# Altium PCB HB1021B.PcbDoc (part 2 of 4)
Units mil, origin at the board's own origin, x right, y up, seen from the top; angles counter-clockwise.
Board outline 4729.44 x 3075.9 mil, 2 copper layers (Top Layer, Bottom Layer); 113 components, 113 nets, 422 pads, 478 vias.
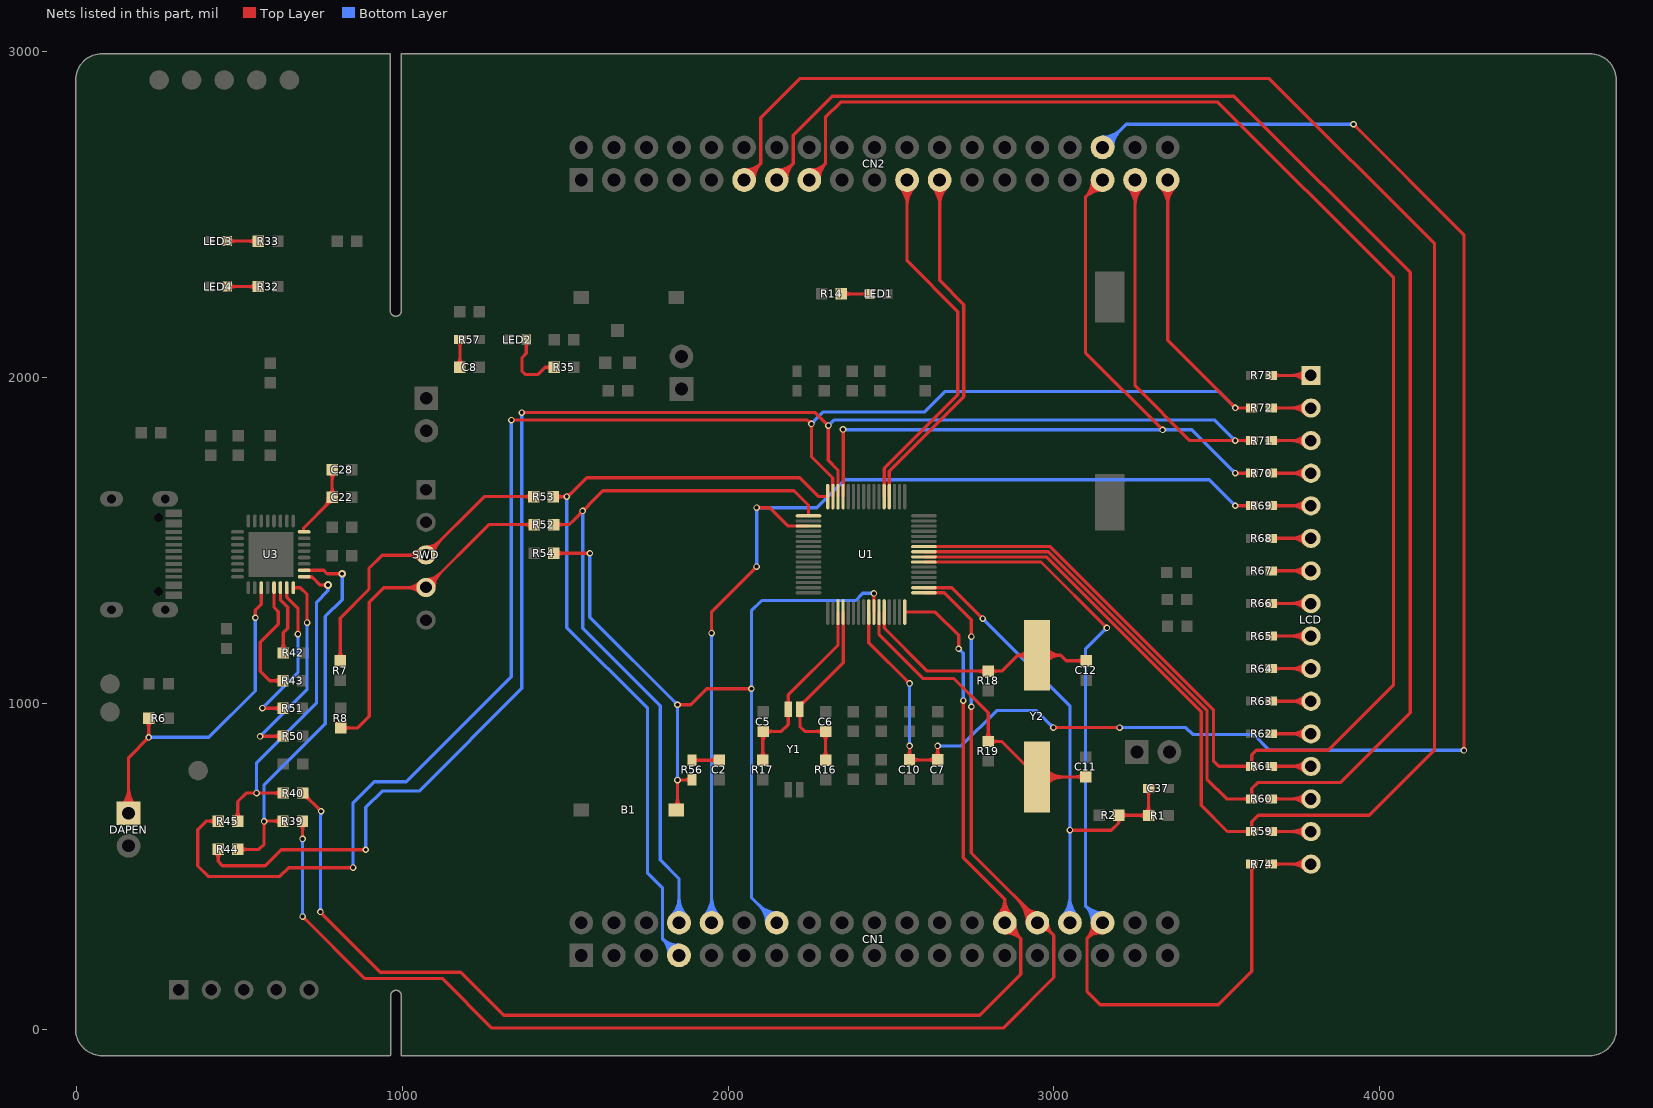
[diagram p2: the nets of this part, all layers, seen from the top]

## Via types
v1: diameter 20, hole 12, Top Layer to Bottom Layer, tented both sides, 451 vias
v2: diameter 23.62, hole 11.81, Top Layer to Bottom Layer, tented both sides, 20 vias
v3: diameter 122.05, hole 122.05, Top Layer to Bottom Layer, tented both sides, 4 vias
v4: diameter 39.37, hole 23.62, Top Layer to Bottom Layer, tented both sides, 2 vias
v5: diameter 30, hole 20, Top Layer to Bottom Layer, tented both sides, 1 vias

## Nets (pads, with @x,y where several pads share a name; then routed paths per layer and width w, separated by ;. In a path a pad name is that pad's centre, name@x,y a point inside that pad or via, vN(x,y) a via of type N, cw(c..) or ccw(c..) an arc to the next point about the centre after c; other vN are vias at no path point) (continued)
LINK_USART_RX: R39.1 R44.1 U3.26 | length 1393
  Top Layer w10: R44.1@495,552 560,552 576,568 v1(576,638) 577,639 R39.1@634,639 ; R44.1@503.84,543.16 cw(c525.18,521.82) 525.18,552 cw(c525.18,582.18) R44.1@503.84,560.84 ; v1@572.46,634.46 cw(c563.93,625.93) 576,625.93 cw(c588.07,625.93) 579.54,634.46 cw(c590.49,623.51) 590.49,639 ; R39.1@625.16,630.16 ccw(c603.82,608.82) 603.82,639 ccw(c603.82,669.18) R39.1@625.16,647.84 ; U3.26@698.97,1408.57 758.82,1408.57 769.09,1398.31 v2(815.61,1398.31) ; v2@810.79,1393.49 ccw(c799.16,1381.86) 799.16,1398.31 ccw(c799.16,1414.75) v2@810.79,1403.12
  Bottom Layer w10: v1@572.46,641.54 ccw(c563.93,650.07) 576,650.07 ccw(c588.07,650.07) v1@579.54,641.54 ; v1(576,638) 576,750 764.06,938.06 764.06,1267.06 815.61,1318.61 v2(815.61,1398.31) ; v2@810.79,1393.49 cw(c799.16,1381.86) 815.61,1381.86 cw(c832.05,1381.86) v2@820.42,1393.49
LINK_USART_TX: R40.1 R45.1 U3.25 | length 1264.5
  Top Layer w10: R45.1@486.16,647.84 ccw(c464.82,669.18) 495,669.18 ccw(c525.18,669.18) R45.1@503.84,647.84 ; R45.1@495,639 495,699 521,725 v1(553,725) R40.1@635,725 ; v1@549.46,721.46 ccw(c540.93,712.93) 540.93,725 ccw(c540.93,737.07) v1@549.46,728.54 ; v1@556.54,721.46 cw(c565.07,712.93) 565.07,725 cw(c565.07,737.07) v1@556.54,728.54 ; R40.1@626.16,716.16 ccw(c604.82,694.82) 604.82,725 ccw(c604.82,755.18) R40.1@626.16,733.84 ; U3.25@697,1388.89 U3.25@698.97,1388.89 723.02,1388.89 748.61,1363.31 v2(772,1363.31) ; U3.25@713.14,1388.38 cw(c713.14,1363.28) 730.89,1381.03 ; U3.25@713.24,1388.39 cw(c716.47,1372.45) 727.97,1383.95 ; v2@767.18,1358.49 ccw(c755.56,1346.86) 755.56,1363.31 ccw(c755.56,1379.75) v2@767.18,1368.12
  Bottom Layer w10: v1@549.46,728.54 ccw(c540.93,737.07) 553,737.07 ccw(c565.07,737.07) v1@556.54,728.54 ; v1(553,725) 553,818 737,1002 737,1311 772,1346 v2(772,1363.31) ; v2@767.18,1358.49 cw(c755.56,1346.86) 772,1346.86 cw(c788.44,1346.86) v2@776.82,1358.49
LXTAL_IN: C5.2 R17.2 U1.3 Y1.1 | length 776.8
  Top Layer w10: R17.2@2098.16,834.84 ccw(c2076.82,856.18) 2107,856.18 ccw(c2137.18,856.18) R17.2@2115.84,834.84 ; C5.2@2099.16,905.16 cw(c2080.23,886.23) 2107,886.23 ; R17.2@2107,826 2107,913 C5.2@2108,914 2164,914 2185.27,935.27 Y1.1@2185.27,982.79 2185.27,1026.27 2337.65,1178.65 U1.3@2337.65,1280.62 ; 2107,881.41 cw(c2140.59,881.41) 2116.84,905.16 cw(c2138.18,883.82) 2138.18,914 cw(c2138.18,944.18) C5.2@2116.84,922.84 ; Y1.1@2180.45,966.16 cw(c2168.83,954.53) 2185.27,954.53 cw(c2201.71,954.53) Y1.1@2190.08,966.16 ; Y1.1@2180.45,999.42 ccw(c2168.83,1011.04) 2185.27,1011.04 ccw(c2201.71,1011.04) Y1.1@2190.08,999.42
LXTAL_OUT: C6.2 R16.2 U1.4 Y1.4 | length 766
  Top Layer w10: Y1.4@2215.88,966.16 cw(c2204.26,954.53) 2220.7,954.53 cw(c2237.14,954.53) Y1.4@2225.52,966.16 ; Y1.4@2220.7,1001.41 ccw(c2220.7,1024.85) 2237.28,1008.28 ; R16.2@2290.77,834.84 ccw(c2269.43,856.17) 2299.61,856.17 ; C6.2@2290.77,922.84 cw(c2269.43,944.18) 2269.43,914 cw(c2269.43,883.82) 2290.77,905.16 cw(c2269.43,883.82) 2299.61,883.82 cw(c2329.78,883.82) C6.2@2308.44,905.16 ; R16.2@2299.61,826 C6.2@2299.61,914 2236,914 2220.7,929.3 Y1.4@2220.7,982.79 2220.7,991.7 2353.4,1124.4 U1.4@2353.4,1280.62 ; 2299.61,856.18 ccw(c2329.79,856.18) R16.2@2308.45,834.84
MCU_SWCLK: R8.2 R52.1 SWD.4 | length 1447.2
  Top Layer w10: R8.2@811,925 863,925 899,961 899,1311 943.21,1355.21 SWD.4@1072,1355.21 ; R8.2@819.84,916.16 cw(c841.18,894.82) 841.18,925 cw(c841.18,955.18) R8.2@819.84,933.84 ; 1011.88,1355.21 ccw(c1011.88,1417.12) SWD.4@1055.66,1373.34 ; 1015.69,1355.21 cw(c1015.69,1298.69) SWD.4@1055.66,1338.66 ; 1036.02,1355.21 ccw(c1036.02,1392.98) SWD.4@1062.73,1366.27 ; 1039.83,1355.21 cw(c1039.83,1322.83) SWD.4@1062.73,1345.73 ; SWD.4@1073,1356 1266,1549 R52.1@1405,1549 ; SWD.4@1073,1370.53 ccw(c1073,1405.6) 1097.8,1380.8 ccw(c1122.6,1356) SWD.4@1087.53,1356 ; SWD.4@1073,1380.53 ccw(c1073,1439.74) 1114.87,1397.87 ccw(c1156.74,1356) SWD.4@1097.53,1356 ; R52.1@1396.16,1540.16 ccw(c1374.82,1518.82) 1374.82,1549 ccw(c1374.82,1579.18) R52.1@1396.16,1557.84
MCU_SWDIO: R7.2 R53.1 SWD.3 | length 1307.3
  Top Layer w10: R7.2@801.16,1139.84 ccw(c779.82,1161.18) 810,1161.18 ccw(c840.18,1161.18) R7.2@818.84,1139.84 ; R7.2@810,1131 810,1261.92 898.07,1349.99 898.07,1415.07 938.21,1455.21 SWD.3@1072,1455.21 ; 1011.88,1455.21 ccw(c1011.88,1517.12) SWD.3@1055.66,1473.34 ; 1015.69,1455.21 cw(c1015.69,1398.69) SWD.3@1055.66,1438.66 ; 1036.02,1455.21 ccw(c1036.02,1492.98) SWD.3@1062.73,1466.27 ; 1039.83,1455.21 cw(c1039.83,1422.83) SWD.3@1062.73,1445.73 ; SWD.3@1073,1456 1252,1635 R53.1@1404,1635 ; SWD.3@1073,1470.53 ccw(c1073,1505.6) 1097.8,1480.8 ccw(c1122.6,1456) SWD.3@1087.53,1456 ; SWD.3@1073,1480.53 ccw(c1073,1539.74) 1114.87,1497.87 ccw(c1156.74,1456) SWD.3@1097.53,1456 ; R53.1@1395.16,1626.16 ccw(c1373.82,1604.82) 1373.82,1635 ccw(c1373.82,1665.18) R53.1@1395.16,1643.84
NetC2_1: C2.1 R56.2 | length 163.7
  Top Layer w10: R56.2@1890,826 C2.1@1973,826 ; R56.2@1896.21,819.79 cw(c1911.2,804.8) 1911.2,826 cw(c1911.2,847.19) R56.2@1896.21,832.21 ; C2.1@1964.16,817.16 ccw(c1942.82,795.82) 1942.82,826 ccw(c1942.82,856.18) C2.1@1964.16,834.84
NetC8_2: C8.2 R57.2 | length 165.7
  Top Layer w10: C8.2@1168.16,2040.84 ccw(c1146.82,2062.18) 1177,2062.18 ccw(c1207.18,2062.18) C8.2@1185.84,2040.84 ; R57.2@1170.79,2110.79 cw(c1155.81,2095.81) 1177,2095.81 cw(c1198.2,2095.81) R57.2@1183.21,2110.79 ; C8.2@1177,2032 R57.2@1177,2117
NetC11_1: C11.1 R19.1 U1.11 Y2.1 | length 1302.2
  Top Layer w10: U1.11@2463.64,1280.62 2463.64,1211.36 2598.69,1076.31 2693.69,1076.31 2798.61,971.39 R19.1@2798.61,883.31 ; R19.1@2789.77,892.15 ccw(c2768.43,913.48) 2798.61,913.48 ccw(c2828.78,913.48) 2807.45,892.15 ccw(c2828.79,913.49) 2828.79,883.31 ccw(c2828.78,853.13) R19.1@2807.45,874.47 ; R19.1@2797.69,883.31 2839.6,883.31 Y2.1@2948.61,774.3 3096.6,774.3 C11.1@3097.61,775.31 ; Y2.1@2965.84,757.07 cw(c3007.44,715.47) 3007.44,774.3 cw(c3007.44,833.13) Y2.1@2965.84,791.53 ; Y2.1@2972.91,750 cw(c3031.58,691.32) 3031.58,774.3 cw(c3031.58,857.28) Y2.1@2972.91,798.6 ; 3065,774.3 ccw(c3065,807.91) C11.1@3088.77,784.14 ; 3069.86,774.3 cw(c3069.86,747.56) C11.1@3088.77,766.47
NetC12_1: C12.1 R18.1 U1.12 Y2.2 | length 1192.2
  Top Layer w10: U1.12@2479.39,1280.62 2479.39,1231.61 2611.69,1099.31 2840.61,1099.31 2889.61,1148.31 ; R18.1@2789.77,1090.47 ccw(c2768.43,1069.13) 2768.43,1099.31 ccw(c2768.43,1129.48) R18.1@2789.77,1108.15 ; R18.1@2807.44,1090.47 cw(c2828.78,1069.13) 2828.78,1099.31 cw(c2828.78,1129.48) R18.1@2807.45,1108.15 ; Y2.2@2918.71,1131.36 ccw(c2889.61,1114.87) 2889.61,1148.31 ; Y2.2@2918.71,1165.26 cw(c2889.61,1181.76) 2889.61,1148.31 ; Y2.2@2927.41,1136.3 ccw(c2906.78,1124.6) 2906.78,1148.31 ccw(c2906.78,1172.03) Y2.2@2927.41,1160.33 ; Y2.2@2967.53,1132.95 cw(c2999.78,1106.77) 2999.78,1148.31 cw(c2999.78,1189.85) Y2.2@2967.53,1163.67 ; Y2.2@2975.29,1126.65 cw(c3020.78,1089.73) 3020.78,1148.31 ; Y2.2@2975.29,1169.98 ccw(c3020.78,1206.9) 3020.78,1148.31 ; C12.1@3090.77,1122.47 ccw(c3069.43,1101.13) 3069.43,1131.31 ccw(c3069.43,1161.49) C12.1@3090.77,1140.15 ; C12.1@3099.61,1131.31 3037.79,1131.31 3020.78,1148.31 ; 2889.61,1148.31 Y2.2@2948.61,1148.31 3020.78,1148.31
NetC22_2: C22.2 C28.2 U3.32 | length 369.8
  Top Layer w10: U3.32@697,1526.68 697,1538.18 781.11,1622.29 784.61,1625.79 C28.2@784.61,1711.79 ; 697,1532.67 ccw(c704.96,1532.67) U3.32@699.33,1527.05 ; 760.02,1601.21 ccw(c728.44,1632.79) C22.2@773.11,1632.79 ; C22.2@774.51,1615.69 cw(c785.61,1604.6) C22.2@785.61,1620.29 ; C22.2@776.77,1641.63 ccw(c757.84,1660.55) 784.61,1660.55 ; C28.2@776.77,1707.95 cw(c757.84,1689.02) 784.61,1689.02 ; 784.61,1665.38 ccw(c818.2,1665.38) C22.2@794.45,1641.63 ; 784.61,1684.2 cw(c818.2,1684.2) C28.2@794.45,1707.95
NetDAPEN_1: DAPEN.1 R6.1 U3.19 | length 1370.8
  Top Layer w10: DAPEN.1@137.78,685.22 ccw(c84.15,738.85) 160,738.85 ccw(c235.85,738.85) DAPEN.1@182.22,685.22 ; DAPEN.1@144.86,678.14 ccw(c108.29,714.71) 160,714.71 ccw(c211.71,714.71) DAPEN.1@175.14,678.14 ; DAPEN.1@160,663 160,834 v1(222,896) R6.1@222,955 ; R6.1@213.16,946.16 cw(c191.82,924.82) 222,924.82 cw(c252.18,924.82) R6.1@230.84,946.16 ; v1@217,896 cw(c204.93,896) 213.46,887.46 cw(c222,878.93) v1@222,891 ; v1@218.46,899.53 ccw(c209.93,908.07) 222,908.07 ccw(c234.07,908.07) v1@225.53,899.53 ; v1@545.46,1266.54 ccw(c536.93,1275.07) 549,1275.07 ccw(c561.07,1275.07) v1@552.54,1266.54 ; v1(549,1263) 549,1285.86 567.08,1303.93 U3.19@567.08,1355.43
  Bottom Layer w10: v1(222,896) 406.71,896 549,1038.28 v1(549,1263) ; v1@225.53,892.46 cw(c234.07,883.93) 234.07,896 cw(c234.07,908.07) v1@225.53,899.53 ; v1@545.46,1259.46 cw(c536.93,1250.93) 549,1250.93 cw(c561.07,1250.93) v1@552.54,1259.46
NetLCD_1: LCD.1 R73.2 | length 302.6
  Top Layer w10: R73.2@3668,2007 LCD.1@3789.2,2007 ; R73.2@3677.93,2000.79 cw(c3692.92,1985.8) 3692.92,2007 cw(c3692.92,2028.2) R73.2@3677.93,2013.21 ; 3729.62,2007 cw(c3729.62,1946.9) LCD.1@3772.11,1989.4 ; 3730.87,2007 ccw(c3730.87,2065.33) LCD.1@3772.11,2024.08 ; 3753.76,2007 cw(c3753.76,1971.04) LCD.1@3779.18,1996.47 ; 3755.01,2007 ccw(c3755.01,2041.19) LCD.1@3779.18,2017.01
NetLCD_2: LCD.2 R72.2 | length 302.6
  Top Layer w10: R72.2@3668,1907 LCD.2@3789.2,1907 ; R72.2@3677.93,1900.79 cw(c3692.92,1885.8) 3692.92,1907 cw(c3692.92,1928.2) R72.2@3677.93,1913.21 ; 3729.62,1907 cw(c3729.62,1846.9) LCD.2@3772.11,1889.4 ; 3730.87,1907 ccw(c3730.87,1965.33) LCD.2@3772.11,1924.08 ; 3753.76,1907 cw(c3753.76,1871.04) LCD.2@3779.18,1896.47 ; 3755.01,1907 ccw(c3755.01,1941.19) LCD.2@3779.18,1917.01
NetLCD_3: LCD.3 R71.2 | length 302.6
  Top Layer w10: R71.2@3668,1807 LCD.3@3789.2,1807 ; R71.2@3677.93,1800.79 cw(c3692.92,1785.8) 3692.92,1807 cw(c3692.92,1828.2) R71.2@3677.93,1813.21 ; 3729.62,1807 cw(c3729.62,1746.9) LCD.3@3772.11,1789.4 ; 3730.87,1807 ccw(c3730.87,1865.33) LCD.3@3772.11,1824.08 ; 3753.76,1807 cw(c3753.76,1771.04) LCD.3@3779.18,1796.47 ; 3755.01,1807 ccw(c3755.01,1841.19) LCD.3@3779.18,1817.01
NetLCD_4: LCD.4 R70.2 | length 302.6
  Top Layer w10: R70.2@3668,1707 LCD.4@3789.2,1707 ; R70.2@3677.93,1700.79 cw(c3692.92,1685.8) 3692.92,1707 cw(c3692.92,1728.2) R70.2@3677.93,1713.21 ; 3729.62,1707 cw(c3729.62,1646.9) LCD.4@3772.11,1689.4 ; 3730.87,1707 ccw(c3730.87,1765.33) LCD.4@3772.11,1724.08 ; 3753.76,1707 cw(c3753.76,1671.04) LCD.4@3779.18,1696.47 ; 3755.01,1707 ccw(c3755.01,1741.19) LCD.4@3779.18,1717.01
NetLCD_5: LCD.5 R69.2 | length 302.6
  Top Layer w10: R69.2@3668,1607 LCD.5@3789.2,1607 ; R69.2@3677.93,1600.79 cw(c3692.92,1585.8) 3692.92,1607 cw(c3692.92,1628.2) R69.2@3677.93,1613.21 ; 3729.62,1607 cw(c3729.62,1546.9) LCD.5@3772.11,1589.4 ; 3730.87,1607 ccw(c3730.87,1665.33) LCD.5@3772.11,1624.08 ; 3753.76,1607 cw(c3753.76,1571.04) LCD.5@3779.18,1596.47 ; 3755.01,1607 ccw(c3755.01,1641.19) LCD.5@3779.18,1617.01
NetLCD_6: LCD.6 R68.2 | length 302.6
  Top Layer w10: R68.2@3668,1507 LCD.6@3789.2,1507 ; R68.2@3677.93,1500.79 cw(c3692.92,1485.8) 3692.92,1507 cw(c3692.92,1528.2) R68.2@3677.93,1513.21 ; 3729.62,1507 cw(c3729.62,1446.9) LCD.6@3772.11,1489.4 ; 3730.87,1507 ccw(c3730.87,1565.33) LCD.6@3772.11,1524.08 ; 3753.76,1507 cw(c3753.76,1471.04) LCD.6@3779.18,1496.47 ; 3755.01,1507 ccw(c3755.01,1541.19) LCD.6@3779.18,1517.01
NetLCD_7: LCD.7 R67.2 | length 302.6
  Top Layer w10: R67.2@3668,1407 LCD.7@3789.2,1407 ; R67.2@3677.93,1400.79 cw(c3692.92,1385.8) 3692.92,1407 cw(c3692.92,1428.2) R67.2@3677.93,1413.21 ; 3729.62,1407 cw(c3729.62,1346.9) LCD.7@3772.11,1389.4 ; 3730.87,1407 ccw(c3730.87,1465.33) LCD.7@3772.11,1424.08 ; 3753.76,1407 cw(c3753.76,1371.04) LCD.7@3779.18,1396.47 ; 3755.01,1407 ccw(c3755.01,1441.19) LCD.7@3779.18,1417.01
NetLCD_8: LCD.8 R66.2 | length 302.6
  Top Layer w10: R66.2@3668,1307 LCD.8@3789.2,1307 ; R66.2@3677.93,1300.79 cw(c3692.92,1285.8) 3692.92,1307 cw(c3692.92,1328.2) R66.2@3677.93,1313.21 ; 3729.62,1307 cw(c3729.62,1246.9) LCD.8@3772.11,1289.4 ; 3730.87,1307 ccw(c3730.87,1365.33) LCD.8@3772.11,1324.08 ; 3753.76,1307 cw(c3753.76,1271.04) LCD.8@3779.18,1296.47 ; 3755.01,1307 ccw(c3755.01,1341.19) LCD.8@3779.18,1317.01
NetLCD_9: LCD.9 R65.2 | length 302.6
  Top Layer w10: R65.2@3668,1207 LCD.9@3789.2,1207 ; R65.2@3677.93,1200.79 cw(c3692.92,1185.8) 3692.92,1207 cw(c3692.92,1228.2) R65.2@3677.93,1213.21 ; 3729.62,1207 cw(c3729.62,1146.9) LCD.9@3772.11,1189.4 ; 3730.87,1207 ccw(c3730.87,1265.33) LCD.9@3772.11,1224.08 ; 3753.76,1207 cw(c3753.76,1171.04) LCD.9@3779.18,1196.47 ; 3755.01,1207 ccw(c3755.01,1241.19) LCD.9@3779.18,1217.01
NetLCD_10: LCD.10 R64.2 | length 302.6
  Top Layer w10: R64.2@3668,1107 LCD.10@3789.2,1107 ; R64.2@3677.93,1100.79 cw(c3692.92,1085.8) 3692.92,1107 cw(c3692.92,1128.2) R64.2@3677.93,1113.21 ; 3729.62,1107 cw(c3729.62,1046.9) LCD.10@3772.11,1089.4 ; 3730.87,1107 ccw(c3730.87,1165.33) LCD.10@3772.11,1124.08 ; 3753.76,1107 cw(c3753.76,1071.04) LCD.10@3779.18,1096.47 ; 3755.01,1107 ccw(c3755.01,1141.19) LCD.10@3779.18,1117.01
NetLCD_11: LCD.11 R63.2 | length 302.6
  Top Layer w10: R63.2@3668,1007 LCD.11@3789.2,1007 ; R63.2@3677.93,1000.79 cw(c3692.92,985.8) 3692.92,1007 cw(c3692.92,1028.2) R63.2@3677.93,1013.21 ; 3729.62,1007 cw(c3729.62,946.9) LCD.11@3772.11,989.4 ; 3730.87,1007 ccw(c3730.87,1065.33) LCD.11@3772.11,1024.08 ; 3753.76,1007 cw(c3753.76,971.04) LCD.11@3779.18,996.47 ; 3755.01,1007 ccw(c3755.01,1041.19) LCD.11@3779.18,1017.01
NetLCD_12: LCD.12 R62.2 | length 302.6
  Top Layer w10: R62.2@3668,907 LCD.12@3789.2,907 ; R62.2@3677.93,900.79 cw(c3692.92,885.8) 3692.92,907 cw(c3692.92,928.2) R62.2@3677.93,913.21 ; 3729.62,907 cw(c3729.62,846.9) LCD.12@3772.11,889.4 ; 3730.87,907 ccw(c3730.87,965.33) LCD.12@3772.11,924.08 ; 3753.76,907 cw(c3753.76,871.04) LCD.12@3779.18,896.47 ; 3755.01,907 ccw(c3755.01,941.19) LCD.12@3779.18,917.01
NetLCD_13: LCD.13 R61.2 | length 303
  Top Layer w10: R61.2@3668,807 3789.2,807 LCD.13@3789.46,806.74 ; R61.2@3677.93,800.79 cw(c3692.92,785.8) 3692.92,807 cw(c3692.92,828.2) R61.2@3677.93,813.21 ; 3729.62,807 cw(c3729.62,746.9) LCD.13@3772.11,789.4 ; 3730.87,807 ccw(c3730.87,865.33) LCD.13@3772.11,824.08 ; 3753.76,807 cw(c3753.76,771.04) LCD.13@3779.18,796.47 ; 3755.01,807 ccw(c3755.01,841.19) LCD.13@3779.18,817.01
NetLCD_14: LCD.14 R60.2 | length 302.6
  Top Layer w10: R60.2@3668,707 LCD.14@3789.2,707 ; R60.2@3677.93,700.79 cw(c3692.92,685.8) 3692.92,707 cw(c3692.92,728.2) R60.2@3677.93,713.21 ; 3729.62,707 cw(c3729.62,646.9) LCD.14@3772.11,689.4 ; 3730.87,707 ccw(c3730.87,765.33) LCD.14@3772.11,724.08 ; 3753.76,707 cw(c3753.76,671.04) LCD.14@3779.18,696.47 ; 3755.01,707 ccw(c3755.01,741.19) LCD.14@3779.18,717.01
NetLCD_15: LCD.15 R59.2 | length 302.6
  Top Layer w10: R59.2@3668,607 LCD.15@3789.2,607 ; R59.2@3677.93,600.79 cw(c3692.92,585.8) 3692.92,607 cw(c3692.92,628.2) R59.2@3677.93,613.21 ; 3729.62,607 cw(c3729.62,546.9) LCD.15@3772.11,589.4 ; 3730.87,607 ccw(c3730.87,665.33) LCD.15@3772.11,624.08 ; 3753.76,607 cw(c3753.76,571.04) LCD.15@3779.18,596.47 ; 3755.01,607 ccw(c3755.01,641.19) LCD.15@3779.18,617.01
NetLCD_16: LCD.16 R74.2 | length 302.6
  Top Layer w10: R74.2@3668,507 LCD.16@3789.2,507 ; R74.2@3677.93,500.79 cw(c3692.92,485.8) 3692.92,507 cw(c3692.92,528.2) R74.2@3677.93,513.21 ; 3729.62,507 cw(c3729.62,446.9) LCD.16@3772.11,489.4 ; 3730.87,507 ccw(c3730.87,565.33) LCD.16@3772.11,524.08 ; 3753.76,507 cw(c3753.76,471.04) LCD.16@3779.18,496.47 ; 3755.01,507 ccw(c3755.01,541.19) LCD.16@3779.18,517.01
NetLED1_1: LED1.1 R14.1 | length 172.3
  Top Layer w10: R14.1@2348,2257 LED1.1@2435,2257 ; R14.1@2356.84,2248.16 cw(c2378.18,2226.82) 2378.18,2257 cw(c2378.18,2287.18) R14.1@2356.84,2265.84 ; LED1.1@2427.93,2249.93 ccw(c2410.86,2232.86) 2410.86,2257 ccw(c2410.86,2281.14) LED1.1@2427.93,2264.07
NetLED2_1: LED2.1 R35.1 | length 295.3
  Top Layer w10: LED2.1@1373.93,2109.93 cw(c1356.86,2092.86) 1381,2092.86 cw(c1405.14,2092.86) LED2.1@1388.07,2109.93 ; LED2.1@1381,2117 1381,2075 1368,2062 1368,2019 1377,2010 1417,2010 1439,2032 ; R35.1@1457.69,2023.65 ccw(c1439,2006.89) 1439,2032 ; R35.1@1457.69,2040.34 cw(c1439,2057.11) 1439,2032 ; R35.1@1467,2032 1439,2032
NetLED3_2: LED3.2 R33.2 | length 181.3
  Top Layer w10: LED3.2@462.61,2419.31 R33.2@558.61,2419.31 ; LED3.2@469.68,2412.24 cw(c486.75,2395.17) 486.75,2419.31 cw(c486.75,2443.45) LED3.2@469.68,2426.38 ; R33.2@549.77,2410.47 ccw(c528.43,2389.13) 528.43,2419.31 ccw(c528.43,2449.49) R33.2@549.77,2428.15
NetLED4_2: LED4.2 R32.2 | length 181.3
  Top Layer w10: LED4.2@462.61,2279.79 R32.2@558.61,2279.79 ; LED4.2@469.68,2272.72 cw(c486.75,2255.65) 486.75,2279.79 cw(c486.75,2303.93) LED4.2@469.68,2286.86 ; R32.2@549.77,2270.95 ccw(c528.43,2249.61) 528.43,2279.79 ccw(c528.43,2309.97) R32.2@549.77,2288.63
NetR42_1: R42.1 U3.22 | length 264.7
  Top Layer w10: U3.22@626.13,1357.39 U3.22@626.13,1355.43 626.13,1318.26 648.61,1295.79 648.61,1230.61 635,1217 R42.1@635,1155 ; R42.1@626.16,1163.84 ccw(c604.82,1185.18) 635,1185.18 ccw(c665.18,1185.18) R42.1@643.84,1163.84
NetR43_1: R43.1 U3.21 | length 416.3
  Top Layer w10: U3.21@606.45,1357.39 U3.21@606.45,1355.43 606.45,1295.03 619.61,1281.88 619.61,1243.61 564,1188 564,1099 593,1070 R43.1@634,1070 ; R43.1@625.16,1061.16 ccw(c603.82,1039.82) 603.82,1070 ccw(c603.82,1100.18) R43.1@625.16,1078.84
NetR50_1: R50.1 U3.24 | length 739.5
  Top Layer w10: v1(564,899) R50.1@634,899 ; v1@567.54,895.46 cw(c576.07,886.93) 576.07,899 cw(c576.07,911.07) v1@567.54,902.54 ; 602.41,899 ccw(c602.41,932.59) R50.1@626.16,908.84 ; 607.24,899 cw(c607.24,872.24) R50.1@626.16,891.16 ; U3.24@665.5,1355.43 686.97,1355.43 708,1334.39 v1(708,1248) ; v1@704.46,1251.54 ccw(c695.93,1260.07) 708,1260.07 ccw(c720.07,1260.07) v1@711.54,1251.54
  Bottom Layer w10: v1(564,899) 708,1043 v1(708,1248) ; v1@564,904 ccw(c564,916.07) 572.54,907.54 ccw(c581.07,899) v1@569,899 ; v1@704.46,1244.46 cw(c695.93,1235.93) 708,1235.93 cw(c720.07,1235.93) v1@711.54,1244.46
NetR51_1: R51.1 U3.23 | length 615.6
  Top Layer w10: v1@571,985 R51.1@634,985 ; v1@574.04,981.96 cw(c581.36,974.64) 581.36,985 ; v1@574.04,989.04 ccw(c583.78,998.78) 583.78,985 ; R51.1@625.16,976.16 ccw(c603.82,954.82) 603.82,985 ccw(c603.82,1015.18) R51.1@625.16,993.84 ; U3.23@645.82,1355.43 645.82,1326.57 679.88,1292.51 v1(679.88,1213.12) ; v1@676.35,1216.65 ccw(c667.81,1225.19) 679.88,1225.19 ccw(c691.95,1225.19) v1@683.42,1216.65
  Bottom Layer w10: v1(570.5,985.5) 679.88,1094.88 v1(679.88,1213.12) ; v1@570.5,990.5 ccw(c570.5,1002.57) 579.04,994.04 ccw(c587.57,985.5) v1@575.5,985.5 ; v1@676.35,1209.58 cw(c667.81,1201.05) 679.88,1201.05 cw(c691.95,1201.05) v1@683.42,1209.58
NRST: B1.2 CN1.14 R54.2 R56.1 U1.10 | length 3333.8
  Top Layer w10: R54.2@1465,1461 v1(1576,1461) ; R54.2@1473.84,1452.16 cw(c1495.18,1430.82) 1495.18,1461 cw(c1495.18,1491.18) R54.2@1473.84,1469.84 ; v1@1572.46,1457.46 ccw(c1563.93,1448.93) 1563.93,1461 ccw(c1563.93,1473.07) v1@1572.46,1464.54 ; B1.2@1834.5,683.38 ccw(c1809.15,708.74) 1845,708.74 ; B1.2@1840.95,673 1845,677.05 v1(1845,765) R56.1@1889,765 ; v1@1841.46,761.46 cw(c1832.93,752.93) 1845,752.93 cw(c1857.07,752.93) 1848.54,761.46 cw(c1857.07,752.93) 1857.07,765 cw(c1857.07,777.07) v1@1848.54,768.54 ; 1845,708.17 ccw(c1880.05,708.17) B1.2@1855.27,683.38 ; v1(1845,996) 1886,996 1935,1045 v1(2072,1045) ; v1@1848.54,992.46 cw(c1857.07,983.93) 1857.07,996 cw(c1857.07,1008.07) v1@1848.54,999.54 ; 1866.39,765 ccw(c1866.39,789.61) R56.1@1883.79,772.21 ; 1871.22,765 cw(c1871.22,747.21) R56.1@1883.79,759.79 ; v1@2068.46,1041.46 ccw(c2059.93,1032.93) 2059.93,1045 ccw(c2059.93,1057.07) v1@2068.46,1048.54 ; v1@2444.35,1334.46 cw(c2435.82,1325.93) 2447.89,1325.93 cw(c2459.96,1325.93) v1@2451.43,1334.46 ; U1.10@2447.89,1280.62 v1(2447.89,1338)
  Bottom Layer w10: v1@1572.46,1457.46 cw(c1563.93,1448.93) 1576,1448.93 cw(c1588.07,1448.93) v1@1579.54,1457.46 ; v1(1576,1461) 1576,1265 v1(1845,996) v1(1845,765) ; v1@1840,996 ccw(c1827.93,996) 1836.46,1004.54 ccw(c1845,1013.07) v1@1845,1001 ; v1@1841.46,768.54 ccw(c1832.93,777.07) 1845,777.07 ccw(c1857.07,777.07) v1@1848.54,768.54 ; v1@1841.46,992.46 cw(c1832.93,983.93) 1845,983.93 cw(c1857.07,983.93) v1@1848.54,992.46 ; v1@2068.46,1041.46 cw(c2059.93,1032.93) 2072,1032.93 cw(c2084.07,1032.93) v1@2075.54,1041.46 ; v1@2068.46,1048.54 ccw(c2059.93,1057.07) 2072,1057.07 ccw(c2084.07,1057.07) v1@2075.54,1048.54 ; CN1.14@2118.19,326.79 ccw(c2042.34,326.79) 2095.97,380.42 ccw(c2149.61,434.05) CN1.14@2149.61,358.21 ; CN1.14@2128.19,326.79 ccw(c2076.48,326.79) 2113.04,363.35 ccw(c2149.61,399.91) CN1.14@2149.61,348.21 ; CN1.14@2148.61,324.62 CN1.14@2148.61,326.79 ; CN1.14@2149.61,326.79 2072,404.39 v1(2072,1045) 2072,1284 2104,1316 2392,1316 2414,1338 v1(2447.89,1338) ; v1@2444.35,1334.46 ccw(c2435.82,1325.93) 2435.82,1338 ccw(c2435.82,1350.07) v1@2444.35,1341.54
PA0: C7.2 C10.2 CN2.34 U1.9 | length 5863.4
  Top Layer w10: U1.9@2432.14,1280.62 2432.14,1186.4 v1(2557.27,1061.27) ; C10.2@2548.43,835.62 ccw(c2527.09,856.96) 2557.27,856.96 ccw(c2587.45,856.96) 2566.11,835.62 ccw(c2587.45,856.96) 2587.45,826.79 ccw(c2587.45,796.61) C10.2@2566.11,817.95 ; v1@2552.27,1061.27 ccw(c2540.2,1061.27) 2548.73,1069.81 ccw(c2557.27,1078.34) v1@2557.27,1066.27 ; v1@2553.73,866.19 cw(c2545.2,857.66) 2557.27,857.66 cw(c2569.34,857.66) v1@2560.81,866.19 ; v1(2557.27,869.73) C10.2@2557.27,826.79 C7.2@2643.6,826.79 v1(2643.6,869.6) ; C7.2@2634.77,817.95 ccw(c2613.43,796.61) 2613.43,826.79 ccw(c2613.43,856.96) 2634.77,835.62 ccw(c2613.43,856.96) 2643.6,856.96 ccw(c2673.78,856.96) C7.2@2652.44,835.62 ; v1@2640.07,866.07 cw(c2631.53,857.53) 2643.6,857.53 cw(c2655.68,857.53) v1@2647.14,866.07 ; v1(2999,926) v1(3202,926) ; v1@3002.54,922.46 cw(c3011.07,913.93) 3011.07,926 cw(c3011.07,938.07) v1@3002.54,929.54 ; v1@3198.46,922.46 ccw(c3189.93,913.93) 3189.93,926 ccw(c3189.93,938.07) v1@3198.46,929.54 ; v1@3920,2773 cw(c3920,2760.93) 3928.54,2769.46 cw(c3937.07,2778) v1@3925,2778 ; v1(3920,2778) 4259,2439 v1(4259,856) ; v1@4255.46,859.54 ccw(c4246.93,868.07) 4259,868.07 ccw(c4271.07,868.07) v1@4262.54,859.54
  Bottom Layer w10: v1@2553.73,873.27 ccw(c2545.2,881.8) 2557.27,881.8 ccw(c2569.34,881.8) v1@2560.81,873.27 ; v1@2553.73,1057.73 cw(c2545.2,1049.2) 2557.27,1049.2 cw(c2569.34,1049.2) v1@2560.81,1057.73 ; v1(2557.27,869.73) v1(2557.27,1061.27) ; v1(2643.6,869.6) 2716.6,869.6 2825,978 2947,978 v1(2999,926) ; v1@2647.14,866.07 cw(c2655.68,857.53) 2655.68,869.6 cw(c2655.68,881.67) v1@2647.14,873.14 ; v1@2994,926 ccw(c2981.93,926) 2990.46,934.54 ccw(c2999,943.07) v1@2999,931 ; CN2.34@3149.61,2706.79 3150.77,2706.79 3221.98,2778 v1(3920,2778) ; CN2.34@3149.61,2728.21 ccw(c3149.61,2782.73) 3188.16,2744.17 ; CN2.34@3149.61,2738.21 ccw(c3149.61,2816.87) 3205.23,2761.25 ; CN2.34@3171.02,2706.79 cw(c3219.91,2706.79) 3185.34,2741.36 ; CN2.34@3181.02,2706.79 cw(c3254.06,2706.79) 3202.41,2758.43 ; v1(3202,926) 3405,926 3426,905 3613,905 3662,856 v1(4259,856) ; v1@3205.54,922.46 cw(c3214.07,913.93) 3214.07,926 cw(c3214.07,938.07) v1@3205.54,929.54 ; v1@3916.46,2774.46 ccw(c3907.93,2765.93) 3907.93,2778 ccw(c3907.93,2790.07) v1@3916.46,2781.54 ; v1@4255.46,852.46 ccw(c4246.93,843.93) 4246.93,856 ccw(c4246.93,868.07) v1@4255.46,859.54
PA1: CN1.28 R40.2 U1.16 | length 4583.1
  Top Layer w10: R40.2@695,712.5 cw(c695,682.32) 716.34,703.66 cw(c737.68,725) R40.2@707.5,725 ; R40.2@695,725 v1(751,669) ; v1@746,669 ccw(c733.93,669) 742.46,677.53 ccw(c751,686.07) v1@751,674 ; v1@751,356 932,175 1179,175 1311,43 2773,43 2899,169 2899,277.39 ; v1@753.99,360 ccw(c770.86,360) 758.93,348.07 ; U1.16@2542.38,1280.62 2636.38,1280.62 2708,1209 v1(2708,1168) ; v1@2704.46,1171.54 ccw(c2695.93,1180.07) 2708,1180.07 ccw(c2720.07,1180.07) v1@2711.54,1171.54 ; v1@2718.46,1005.46 cw(c2709.93,996.93) 2722,996.93 cw(c2734.07,996.93) v1@2725.54,1005.46 ; v1(2722,1009) 2722,527 2849.61,399.39 ; CN1.28@2828.1,349.69 ccw(c2781.43,399.39) 2849.61,399.39 ; CN1.28@2834.95,342.4 ccw(c2803.13,376.28) 2849.61,376.28 ccw(c2896.08,376.28) CN1.28@2864.27,342.4 ; CN1.28@2850.89,305.41 cw(c2853.42,263.26) 2883.28,293.12 cw(c2913.13,322.97) CN1.28@2870.99,325.5 ; CN1.28@2851.49,295.43 cw(c2855.2,233.6) 2899,277.4 ; CN1.28@2871.11,349.69 cw(c2917.78,399.39) 2849.61,399.39 ; CN1.28@2880.97,324.91 ccw(c2942.8,321.19) 2899,277.4 ; 2849.61,399.39 CN1.28@2849.61,326.79 2899,277.39
  Bottom Layer w10: v1@745.45,363.54 ccw(c736.92,372.07) 748.99,372.07 ccw(c761.06,372.07) v1@752.52,363.54 ; v1(748.99,360) v1@748.99,666.99 ; 748.99,652.07 cw(c767.93,652.07) v1@754.54,665.46 ; v1@2708,1163 cw(c2708,1150.93) 2716.54,1159.46 cw(c2725.07,1168) v1@2713,1168 ; v1(2708,1168) 2722,1154 v1(2722,1009) ; v1@2718.46,1012.54 ccw(c2709.93,1021.07) 2722,1021.07 ccw(c2734.07,1021.07) v1@2725.54,1012.54
PA2: CN1.30 R39.2 U1.17 | length 4691.9
  Top Layer w10: R39.2@685.16,630.16 cw(c663.82,608.82) 694,608.82 cw(c724.18,608.82) R39.2@702.84,630.16 ; v1@690.46,587.54 ccw(c681.93,596.07) 694,596.07 ccw(c706.07,596.07) v1@697.53,587.54 ; v1@694,341 cw(c694,328.93) 702.53,337.47 cw(c711.07,346) v1@699,346 ; v1(694,346) 884,156 1123,156 1275.39,3.61 2844.77,3.61 3000,158.84 3000,288 2747,541 v1(2747,990) ; v1(694,584) R39.2@694,639 ; U1.17@2601.43,1339.68 2664.32,1339.68 2747,1257 v1(2747,1205) ; v1@2743.46,986.46 cw(c2734.93,977.93) 2747,977.93 cw(c2759.07,977.93) v1@2750.54,986.46 ; v1@2743.46,1208.54 ccw(c2734.93,1217.07) 2747,1217.07 ccw(c2759.07,1217.07) v1@2750.54,1208.54 ; 2887.77,400.23 cw(c2814.32,326.79) CN1.30@2918.19,326.79 ; 2904.84,383.16 cw(c2848.46,326.79) CN1.30@2928.19,326.79 ; 2915.79,372.21 ccw(c2949.61,406.03) CN1.30@2949.61,358.21 ; 2921.91,366.09 cw(c2882.61,326.79) CN1.30@2938.19,326.79 ; CN1.30@2954.48,305.93 cw(c2963.88,265.71) 2993.08,294.92 ; CN1.30@2981.02,326.79 ccw(c3028.85,326.79) 2995.03,292.97
  Bottom Layer w10: v1@690.46,349.54 ccw(c681.93,358.07) 694,358.07 ccw(c706.07,358.07) v1@697.53,349.54 ; v1@690.46,580.47 cw(c681.93,571.93) 694,571.93 cw(c706.07,571.93) v1@697.53,580.47 ; v1(694,346) v1(694,584) ; v1@2743.46,993.54 ccw(c2734.93,1002.07) 2747,1002.07 ccw(c2759.07,1002.07) v1@2750.54,993.54 ; v1@2743.46,1201.46 cw(c2734.93,1192.93) 2747,1192.93 cw(c2759.07,1192.93) v1@2750.54,1201.46 ; v1(2747,990) v1(2747,1205)
PA3: C37.1 CN1.32 R1.1 R2.2 U1.18 | length 2125.1
  Top Layer w10: U1.18@2601.43,1355.43 2686.77,1355.43 v1(2782,1260.2) ; v1@2777,1260.2 ccw(c2764.93,1260.2) 2773.46,1268.73 ccw(c2782,1277.27) v1@2782,1265.2 ; v1(3049.61,611) 3177,611 3199,633 ; v1@3053.14,607.46 cw(c3061.68,598.93) 3061.68,611 cw(c3061.68,623.07) v1@3053.14,614.54 ; R2.2@3191.83,646.76 cw(c3182.21,633) 3199,633 ; R2.2@3206.17,646.76 ccw(c3215.79,633) 3199,633 ; R2.2@3207.84,648.16 cw(c3229.18,626.82) 3229.18,657 cw(c3229.18,687.18) R2.2@3207.84,665.84 ; 3258.41,657 cw(c3258.41,623.41) R1.1@3282.16,647.16 ; 3263.24,657 ccw(c3263.24,683.76) 3282.16,664.84 ccw(c3260.82,686.18) 3291,686.18 ccw(c3321.18,686.18) R1.1@3299.84,664.84 ; C37.1@3284.79,732.79 cw(c3269.8,717.8) 3291,717.8 cw(c3312.2,717.8) C37.1@3297.21,732.79 ; C37.1@3291,739 R1.1@3291,656 3290,657 R2.2@3199,657 3199,633
  Bottom Layer w10: v1@2782,1255.2 cw(c2782,1243.12) 2790.54,1251.66 cw(c2799.07,1260.2) v1@2787,1260.2 ; v1(2782,1260.2) 3049.61,992.59 v1(3049.61,611) CN1.32@3049.61,326.79 ; CN1.32@3027.39,349 ccw(c2973.76,402.64) 3049.61,402.64 ccw(c3125.45,402.64) CN1.32@3071.82,349 ; CN1.32@3034.46,341.93 ccw(c2997.9,378.49) 3049.61,378.49 ccw(c3101.31,378.49) CN1.32@3064.75,341.93 ; v1@3046.07,607.46 cw(c3037.54,598.93) 3049.61,598.93 cw(c3061.68,598.93) v1@3053.14,607.46 ; v1@3046.07,614.54 ccw(c3037.54,623.07) 3049.61,623.07 ccw(c3061.68,623.07) v1@3053.14,614.54
PA4: CN1.34 R74.1 U1.23 | length 3155.4
  Top Layer w10: U1.23@2601.43,1434.17 2960.83,1434.17 v1(3163,1232) ; CN1.34@3118.32,323.94 cw(c3062.7,318.87) 3102.19,279.37 ; CN1.34@3128.28,324.84 cw(c3090.36,321.39) 3117.28,294.46 cw(c3144.21,267.54) CN1.34@3147.66,305.46 ; CN1.34@3146.75,295.5 ccw(c3141.68,239.88) 3102.19,279.37 ; CN1.34@3149.61,326.79 3102.19,279.37 ; v1@3158,1232 ccw(c3145.93,1232) 3154.46,1240.54 ccw(c3163,1249.07) v1@3163,1237 ; R74.1@3601.79,500.79 cw(c3586.8,485.8) 3608,485.8 cw(c3629.2,485.8) R74.1@3614.21,500.79 ; R74.1@3608,507 3608,177.79 3505.02,74.81 3143,74.81 3102.19,115.62 3102.19,279.37
  Bottom Layer w10: CN1.34@3118.19,327.22 ccw(c3045.83,328.22) 3097,379.39 ; CN1.34@3128.19,327.08 ccw(c3078.86,327.76) 3113.75,362.65 ccw(c3148.63,397.53) CN1.34@3149.31,348.2 ; CN1.34@3149.17,358.2 cw(c3148.18,430.57) 3097,379.39 ; CN1.34@3149.61,326.79 3097,379.39 ; v1@3158,1232 cw(c3145.93,1232) 3154.46,1223.46 cw(c3163,1214.93) v1@3163,1227 ; v1(3163,1232) 3097,1166 3097,379.39
PA5: CN2.11 R59.1 U1.24 | length 6549.8
  Top Layer w10: CN2.11@2049.61,2606.79 2100.19,2657.37 ; CN2.11@2050.51,2628.19 ccw(c2052.41,2672.95) 2084.09,2641.27 ccw(c2115.77,2609.59) CN2.11@2071,2607.69 ; CN2.11@2050.94,2638.18 ccw(c2053.71,2703.84) 2100.19,2657.37 ; CN2.11@2081,2608.12 cw(c2146.66,2610.9) 2100.19,2657.37 ; U1.24@2601.43,1449.91 2977.09,1449.91 3453,974 3453,687 3533,607 R59.1@3608,607 3608,637 3628,657 3968,657 4169,858 4169,2411 3662,2918 2219.87,2918 2100.19,2798.32 2100.19,2657.37 ; R59.1@3598.07,600.79 ccw(c3583.08,585.8) 3583.08,607 ccw(c3583.08,628.2) R59.1@3598.07,613.21 ; R59.1@3601.79,613.21 ccw(c3586.8,628.2) 3608,628.2 ccw(c3629.2,628.2) R59.1@3614.21,613.21
PA6: CN2.13 R60.1 U1.25 | length 5985.4
  Top Layer w10: CN2.13@2149.61,2606.79 2200.19,2657.37 ; CN2.13@2150.51,2628.19 ccw(c2152.41,2672.95) 2184.09,2641.27 ccw(c2215.77,2609.59) CN2.13@2171,2607.69 ; CN2.13@2150.94,2638.18 ccw(c2153.71,2703.84) 2200.19,2657.37 ; CN2.13@2181,2608.12 cw(c2246.66,2610.9) 2200.19,2657.37 ; U1.25@2601.43,1465.66 2983.49,1465.66 3470,979.15 3470,768 3531,707 R60.1@3608,707 3608,739 3626,757 3879,757 4094,972 4094,2323 3553,2864 2320.12,2864 2200.19,2744.07 2200.19,2657.37 ; R60.1@3598.07,700.79 ccw(c3583.08,685.8) 3583.08,707 ccw(c3583.08,728.2) R60.1@3598.07,713.21 ; R60.1@3601.79,713.21 ccw(c3586.8,728.2) 3608,728.2 ccw(c3629.2,728.2) R60.1@3614.21,713.21
PA7: CN2.15 R61.1 U1.26 | length 5629.1
  Top Layer w10: CN2.15@2249.61,2606.79 2299.02,2656.2 ; CN2.15@2250.88,2628.17 ccw(c2253.4,2670.37) 2283.29,2640.47 ccw(c2313.18,2610.58) CN2.15@2270.99,2608.06 ; CN2.15@2251.48,2638.15 ccw(c2255.17,2700.05) 2299.02,2656.2 ; CN2.15@2280.97,2608.66 cw(c2342.87,2612.35) 2299.02,2656.2 ; U1.26@2601.43,1481.41 2988.95,1481.41 3490,980.36 3490,824 3507,807 R61.1@3608,807 3608,842 3622,856 3842,856 4043,1057 4043,2307 3504,2846 2345.52,2846 2299.02,2799.51 2299.02,2656.2 ; R61.1@3598.07,800.79 ccw(c3583.08,785.8) 3583.08,807 ccw(c3583.08,828.2) R61.1@3598.07,813.21 ; R61.1@3601.79,813.21 ccw(c3586.8,828.2) 3608,828.2 ccw(c3629.2,828.2) R61.1@3614.21,813.21
PA8: CN2.23 U1.36 | length 1297.8
  Top Layer w10: U1.36@2495.13,1634.95 2495.13,1713.13 2724,1942 2724,2224 2649.61,2298.39 CN2.23@2649.61,2606.79 ; CN2.23@2627.39,2584.57 cw(c2573.76,2530.94) 2649.61,2530.94 cw(c2725.45,2530.94) CN2.23@2671.82,2584.57 ; CN2.23@2634.46,2591.64 cw(c2597.9,2555.08) 2649.61,2555.08 cw(c2701.31,2555.08) CN2.23@2664.75,2591.64
PA9: CN2.21 U1.37 | length 1330
  Top Layer w10: U1.37@2479.39,1634.95 2479.39,1721.39 2705,1947 2705,2203 2549.61,2358.39 CN2.21@2549.61,2606.79 ; CN2.21@2527.39,2584.57 cw(c2473.76,2530.94) 2549.61,2530.94 cw(c2625.45,2530.94) CN2.21@2571.82,2584.57 ; CN2.21@2534.46,2591.64 cw(c2497.9,2555.08) 2549.61,2555.08 cw(c2601.31,2555.08) CN2.21@2564.75,2591.64
PA10: CN2.33 R70.1 U1.45 | length 2757.4
  Top Layer w10: v1@2349.46,1837.46 cw(c2339.96,1827.96) 2353.4,1827.96 ; v1(2353,1841) v1@2353.37,1841 ; U1.45@2353.4,1634.95 v1@2353.4,1840.97 ; 2353.4,1829.9 cw(c2364.1,1829.9) v1@2356.54,1837.46 ; CN2.33@3118.19,2606.35 cw(c3045.83,2605.36) 3097,2554.19 ; CN2.33@3128.19,2606.49 cw(c3078.86,2605.81) 3113.75,2570.93 cw(c3148.63,2536.04) CN2.33@3149.31,2585.37 ; CN2.33@3149.17,2575.37 ccw(c3148.18,2503.01) 3097,2554.18 ; CN2.33@3149.61,2606.79 3097,2554.18 ; v1@3329,1840 ccw(c3316.93,1840) 3325.46,1848.54 ccw(c3334,1857.07) v1@3334,1845 ; v1(3334,1840) 3097,2077 3097,2554.18 ; v1(3557,1707) R70.1@3608,1707 ; v1@3560.54,1703.46 cw(c3569.07,1694.93) 3569.07,1707 cw(c3569.07,1719.07) v1@3560.54,1710.54 ; R70.1@3598.07,1700.79 ccw(c3583.08,1685.8) 3583.08,1707 ccw(c3583.08,1728.2) R70.1@3598.07,1713.21
  Bottom Layer w10: v1(2353,1841) 2354,1840 3424,1840 v1(3557,1707) ; v1@2356.54,1844.54 ccw(c2367.49,1855.49) 2367.49,1840 ; v1@3330.46,1836.46 ccw(c3321.93,1827.93) 3321.93,1840 ccw(c3321.93,1852.07) v1@3330.46,1843.54 ; v1@3337.54,1836.46 cw(c3346.07,1827.93) 3346.07,1840 cw(c3346.07,1852.07) v1@3337.54,1843.54 ; v1@3552,1707 ccw(c3539.93,1707) 3548.46,1715.54 ccw(c3557,1724.07) v1@3557,1712
PA11: CN2.35 R44.2 R71.1 U1.46 | length 6123.1
  Top Layer w10: R44.2@426.16,543.16 cw(c404.82,521.82) 435,521.82 cw(c465.18,521.82) R44.2@443.84,543.16 ; R44.2@435,552 435,515 448,502 579,502 628,551 v1(888,551) ; v1@884.46,547.46 ccw(c875.93,538.93) 875.93,551 ccw(c875.93,563.07) v1@884.46,554.54 ; v1(1367,1893) 2268,1893 v1(2308,1853) 2308,1746 2337.65,1716.35 U1.46@2337.65,1634.95 ; v1@1370.54,1889.46 cw(c1379.07,1880.93) 1379.07,1893 cw(c1379.07,1905.07) v1@1370.54,1896.54 ; v1@2303,1853 ccw(c2290.93,1853) 2299.46,1861.54 ccw(c2308,1870.07) v1@2308,1858 ; v1@2304.46,1849.46 cw(c2295.93,1840.93) 2308,1840.93 cw(c2320.07,1840.93) v1@2311.54,1849.46 ; CN2.35@3227.39,2584.57 cw(c3173.76,2530.94) 3249.61,2530.94 cw(c3325.45,2530.94) CN2.35@3271.82,2584.57 ; CN2.35@3234.46,2591.64 cw(c3197.9,2555.08) 3249.61,2555.08 cw(c3301.31,2555.08) CN2.35@3264.75,2591.64 ; CN2.35@3249.61,2606.79 3249.61,1975.39 3418,1807 v1(3557,1807) R71.1@3608,1807 ; v1@3553.46,1803.46 ccw(c3544.93,1794.93) 3544.93,1807 ccw(c3544.93,1819.07) v1@3553.46,1810.54 ; v1@3560.54,1803.46 cw(c3569.07,1794.93) 3569.07,1807 cw(c3569.07,1819.07) v1@3560.54,1810.54 ; R71.1@3598.07,1800.79 ccw(c3583.08,1785.8) 3583.08,1807 ccw(c3583.08,1828.2) R71.1@3598.07,1813.21
  Bottom Layer w10: v1@884.46,554.54 ccw(c875.93,563.07) 888,563.07 ccw(c900.07,563.07) v1@891.54,554.54 ; v1(888,551) 888,681 938,731 1052,731 1367,1046 v1(1367,1893) ; v1@1363.46,1889.46 cw(c1354.93,1880.93) 1367,1880.93 cw(c1379.07,1880.93) v1@1370.54,1889.46 ; v1(2308,1853) 2325,1870 3494,1870 v1(3557,1807) ; v1@2308,1858 ccw(c2308,1870.07) 2316.54,1861.54 ccw(c2325.07,1853) v1@2313,1853 ; v1@3552,1807 ccw(c3539.93,1807) 3548.46,1815.54 ccw(c3557,1824.07) v1@3557,1812
PA12: CN2.37 R45.2 R72.1 U1.47 | length 6167.6
  Top Layer w10: R45.2@426.16,630.16 ccw(c404.82,608.82) 404.82,639 ccw(c404.82,669.18) R45.2@426.16,647.84 ; R45.2@435,639 398,639 372,613 372,501 404,469 624,469 651,496 v1(849,496) ; v1@845.46,492.46 ccw(c836.93,483.93) 836.93,496 ccw(c836.93,508.07) v1@845.46,499.54 ; v1(1335,1870) 2244,1870 v1(2256,1858) 2256,1758 2321.91,1692.09 U1.47@2321.91,1634.95 ; v1@1338.54,1866.46 cw(c1347.07,1857.93) 1347.07,1870 cw(c1347.07,1882.07) v1@1338.54,1873.54 ; v1@2251,1858 ccw(c2238.93,1858) 2247.46,1866.54 ccw(c2256,1875.07) v1@2256,1863 ; v1@2252.46,1854.46 cw(c2243.93,1845.93) 2256,1845.93 cw(c2268.07,1845.93) v1@2259.54,1854.46 ; CN2.37@3327.39,2584.57 cw(c3273.76,2530.94) 3349.61,2530.94 cw(c3425.45,2530.94) CN2.37@3371.82,2584.57 ; CN2.37@3334.46,2591.64 cw(c3297.9,2555.08) 3349.61,2555.08 cw(c3401.31,2555.08) CN2.37@3364.75,2591.64 ; CN2.37@3349.61,2606.79 3349.61,2114.39 v1(3557,1907) R72.1@3608,1907 ; v1@3552,1907 ccw(c3539.93,1907) 3548.46,1915.54 ccw(c3557,1924.07) v1@3557,1912 ; v1@3560.54,1903.46 cw(c3569.07,1894.93) 3569.07,1907 cw(c3569.07,1919.07) v1@3560.54,1910.54 ; R72.1@3598.07,1900.79 ccw(c3583.08,1885.8) 3583.08,1907 ccw(c3583.08,1928.2) R72.1@3598.07,1913.21
  Bottom Layer w10: v1@845.46,499.54 ccw(c836.93,508.07) 849,508.07 ccw(c861.07,508.07) v1@852.54,499.54 ; v1(849,496) 849,695 914,760 1013,760 1335,1082 v1(1335,1870) ; v1@1331.46,1866.46 cw(c1322.93,1857.93) 1335,1857.93 cw(c1347.07,1857.93) v1@1338.54,1866.46 ; v1(2256,1858) 2293,1895 2604,1895 2666.79,1957.79 3506.21,1957.79 v1(3557,1907) ; v1@2256,1863 ccw(c2256,1875.07) 2264.54,1866.54 ccw(c2273.07,1858) v1@2261,1858 ; v1@3552,1907 ccw(c3539.93,1907) 3548.46,1915.54 ccw(c3557,1924.07) v1@3557,1912
PA13: CN1.7 R53.2 U1.48 | length 2724.6
  Top Layer w10: R53.2@1464,1635 v1(1505,1635) 1508,1635 1566,1693 2220,1693 2278.05,1634.95 U1.48@2306.16,1634.95 ; R53.2@1472.84,1626.16 cw(c1494.18,1604.82) 1494.18,1635 cw(c1494.18,1665.18) R53.2@1472.84,1643.84 ; v1@1501.46,1631.46 ccw(c1492.93,1622.93) 1492.93,1635 ccw(c1492.93,1647.07) v1@1501.46,1638.54 ; v1@1505,1640 ccw(c1505,1659.31) 1518.66,1645.66
  Bottom Layer w10: v1@1501.46,1631.46 cw(c1492.93,1622.93) 1505,1622.93 cw(c1517.07,1622.93) v1@1508.54,1631.46 ; v1(1505,1635) 1505,1233 1753,985 1753,479 1799.02,432.98 1799.02,277.37 ; CN1.7@1818.22,228.12 ccw(c1752.56,230.9) 1799.03,277.37 ; CN1.7@1828.21,227.69 ccw(c1783.45,229.59) 1815.13,261.27 ccw(c1846.81,292.95) CN1.7@1848.7,248.19 ; CN1.7@1848.28,258.18 cw(c1845.5,323.84) 1799.03,277.37 ; CN1.7@1849.61,226.79 1799.02,277.37
PA14: CN1.8 R52.2 U1.49 | length 2567.5
  Top Layer w10: R52.2@1465,1549 1511.95,1549 1528.95,1566 1615.95,1653 2202.54,1653 2247.1,1608.44 U1.49@2247.1,1575.9 ; R52.2@1473.84,1540.16 cw(c1495.18,1518.82) 1495.18,1549 cw(c1495.18,1579.18) R52.2@1473.84,1557.84 ; v1@1548.86,1590.91 cw(c1536.79,1590.91) 1545.32,1582.38 cw(c1553.86,1573.84) v1@1553.86,1585.91 ; v1@1553.86,1595.91 ccw(c1553.86,1607.98) 1562.39,1599.45 ccw(c1570.93,1590.91) v1@1558.86,1590.91
  Bottom Layer w10: v1@1550.32,1587.38 cw(c1541.79,1578.84) 1553.86,1578.84 cw(c1565.93,1578.84) v1@1557.39,1587.38 ; v1(1553.86,1590.91) 1553.86,1231.14 1791.81,993.19 1791.81,520.19 1849.61,462.39 CN1.8@1849.61,326.79 ; CN1.8@1827.39,349 ccw(c1773.76,402.64) 1849.61,402.64 ccw(c1925.45,402.64) CN1.8@1871.82,349 ; CN1.8@1834.46,341.93 ccw(c1797.9,378.49) 1849.61,378.49 ccw(c1901.31,378.49) CN1.8@1864.75,341.93
PA15: CN1.10 R69.1 U1.51 | length 3511.8
  Top Layer w10: v1@1946.07,1219.54 ccw(c1937.54,1228.07) 1949.61,1228.07 ccw(c1961.68,1228.07) v1@1953.14,1219.54 ; v1(1949.61,1216) 1949.61,1281.61 v1(2088,1420) ; v1@2083,1420 cw(c2070.93,1420) 2079.46,1411.46 cw(c2088,1402.93) v1@2088,1415 ; v1(2088,1601) 2128,1601 2184.6,1544.4 U1.51@2247.1,1544.4 ; v1@2091.54,1597.46 cw(c2100.07,1588.93) 2100.07,1601 cw(c2100.07,1613.07) v1@2091.54,1604.54 ; v1(3557,1607) R69.1@3608,1607 ; v1@3560.54,1603.46 cw(c3569.07,1594.93) 3569.07,1607 cw(c3569.07,1619.07) v1@3560.54,1610.54 ; R69.1@3598.07,1600.79 ccw(c3583.08,1585.8) 3583.08,1607 ccw(c3583.08,1628.2) R69.1@3598.07,1613.21
  Bottom Layer w8: CN1.10@1949.61,306.79 CN1.10@1949.61,311.41
  Bottom Layer w10: CN1.10@1927.39,349 ccw(c1873.76,402.64) 1949.61,402.64 ccw(c2025.45,402.64) CN1.10@1971.82,349 ; CN1.10@1934.46,341.93 ccw(c1897.9,378.49) 1949.61,378.49 ccw(c2001.31,378.49) CN1.10@1964.75,341.93 ; v1@1946.07,1212.46 cw(c1937.54,1203.93) 1949.61,1203.93 cw(c1961.68,1203.93) v1@1953.14,1212.46 ; CN1.10@1949.61,326.79 v1(1949.61,1216) ; v1@2084.46,1423.54 ccw(c2075.93,1432.07) 2088,1432.07 ccw(c2100.07,1432.07) v1@2091.54,1423.54 ; v1@2084.46,1597.46 cw(c2075.93,1588.93) 2088,1588.93 cw(c2100.07,1588.93) 2091.54,1597.46 cw(c2100.07,1588.93) 2100.07,1601 cw(c2100.07,1613.07) v1@2091.54,1604.54 ; v1(2088,1420) v1(2088,1601) 2272.2,1601 2358.2,1687 3477,1687 v1(3557,1607) ; v1@3552,1607 ccw(c3539.93,1607) 3548.46,1615.54 ccw(c3557,1624.07) v1@3557,1612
